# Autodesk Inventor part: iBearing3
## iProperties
Shininess: 86.0
Length Units: 11269
Angle Units: 11279
Time Units: 11290
Mass Units: 11286
Length Display Precision: 3
Angle Display Precision: 2
Compacted: True
Created: 2000-11
Part Number: iBearing3
User Status: release
Material: Steel, High Strength Low Alloy
Document SubType Name: Modeling
Designer: Administrator
Density: 7.84
Volumn: 10.92938973139743
Area: 86.70517834789415
PropertySet Name: Model Information
Control State: 0
Master: False
Checked Out: False
Author: Administrator
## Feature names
1. Shield [Revolution]
